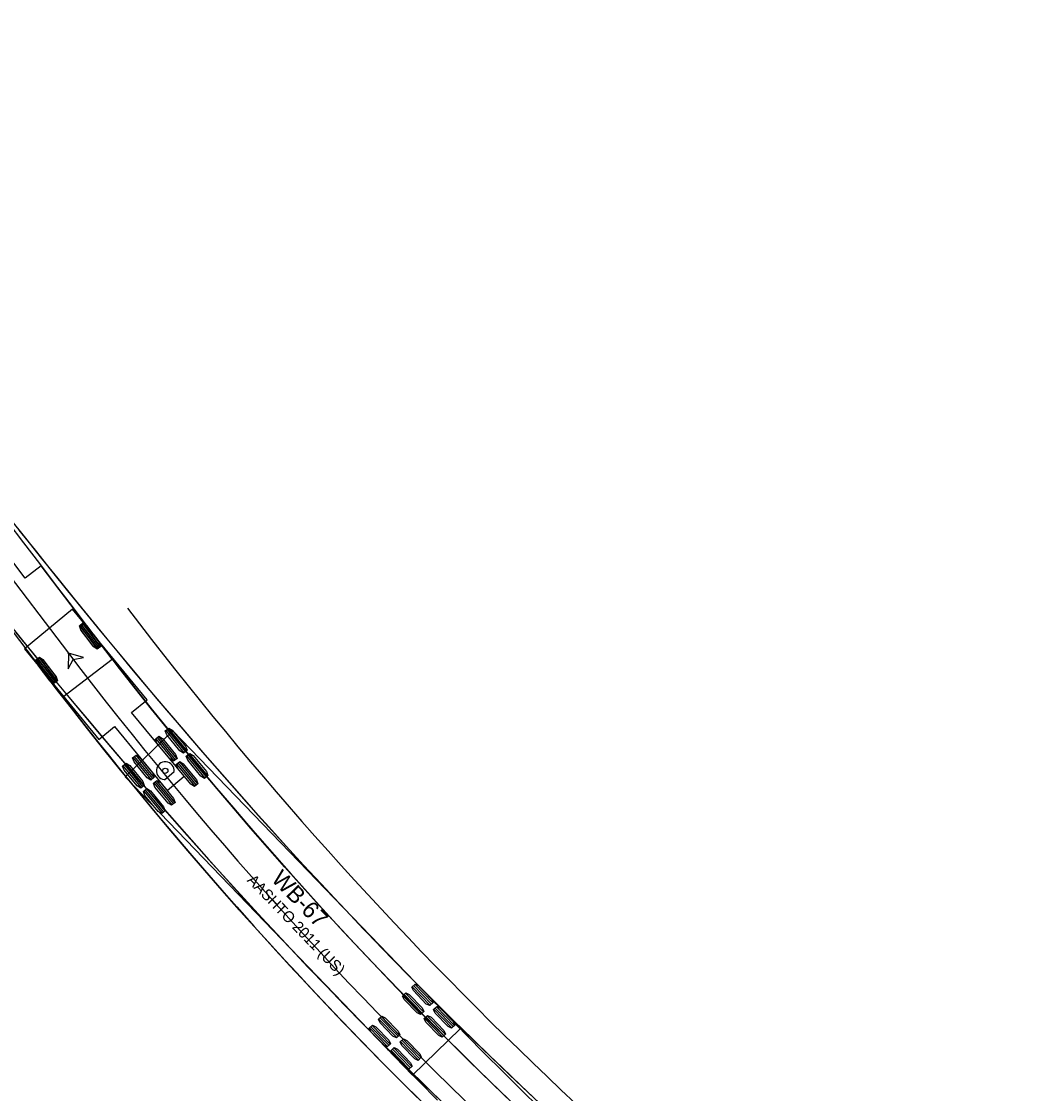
# Model space of a CAD drawing. Extents: x 916040 to 917457, y 328936 to 330267.
# Drawn here: x 916379 to 916508.8, y 330071.7 to 330208.9 of the extents above; entities that cross this region are included whole.
import ezdxf

# ---------------------------------------------------------------- set-up
doc = ezdxf.new("R2010")
doc.units = 0
for name, color, linetype in [('SB_LeftontoRoute25_WB67', 7, 'Continuous'), ('SB_RightontoRoute25_WB67_v2', 7, 'Continuous'), ('SB_ThruontonSacoRd_WB67', 7, 'Continuous'), ('WB_RightontoManchester_WB67', 7, 'Continuous')]:
    doc.layers.add(name, color=color, linetype=linetype)

msp = doc.modelspace()

# ---------------------------------------------------------------- linework, layer by layer
at = {"layer": 'SB_LeftontoRoute25_WB67'}
for p, q in [((916379.47, 330137.69), (916373.05, 330146.12)), ((916381.52, 330139.25), (916379.47, 330137.69)), ((916390.61, 330127.32), (916381.52, 330139.25)), ((916375.15, 330134.4), (916384.24, 330122.47)), ((916388.75, 330128.63), (916386.52, 330131.54)), ((916388.93, 330128.76), (916386.71, 330131.68)), ((916389.11, 330128.9), (916386.89, 330131.82)), ((916383.11, 330124.33), (916380.89, 330127.25)), ((916383.3, 330124.47), (916381.07, 330127.39)), ((916383.48, 330124.61), (916381.26, 330127.53)), ((916384.24, 330122.47), (916390.61, 330127.32)), ((916390.61, 330127.32), (916390.61, 330127.32))]:
    msp.add_line(p, q, dxfattribs=at)
for points in [[(916377.44, 330145.41), (916379.5, 330142.8), (916381.57, 330140.21), (916383.64, 330137.62), (916385.73, 330135.04), (916387.82, 330132.47), (916389.93, 330129.91), (916392.04, 330127.36), (916394.16, 330124.82), (916396.29, 330122.28), (916398.44, 330119.76), (916400.59, 330117.25), (916402.76, 330114.75), (916404.93, 330112.26), (916407.12, 330109.78), (916409.32, 330107.32), (916411.54, 330104.86), (916413.76, 330102.42), (916416, 330099.99), (916418.25, 330097.57), (916420.51, 330095.17), (916422.79, 330092.78), (916425.08, 330090.4), (916427.38, 330088.03), (916429.7, 330085.68), (916432.03, 330083.34), (916434.37, 330081.02), (916436.73, 330078.71), (916439.1, 330076.41), (916441.48, 330074.13), (916443.87, 330071.86), (916446.28, 330069.61)], [(916377.02, 330132.29), (916379.13, 330129.69), (916381.24, 330127.09), (916383.37, 330124.51), (916385.5, 330121.93), (916387.65, 330119.36), (916389.8, 330116.8), (916391.97, 330114.25), (916394.15, 330111.7), (916396.34, 330109.17), (916398.55, 330106.65), (916400.76, 330104.14), (916402.99, 330101.64), (916405.24, 330099.16), (916407.49, 330096.68), (916409.76, 330094.22), (916412.04, 330091.77), (916414.34, 330089.33), (916416.65, 330086.9), (916418.97, 330084.49), (916421.31, 330082.09), (916423.66, 330079.7), (916426.02, 330077.33), (916428.4, 330074.97), (916430.79, 330072.62), (916433.2, 330070.29)], [(916388.18, 330130.5), (916390.21, 330127.86), (916392.25, 330125.23), (916394.31, 330122.62), (916396.38, 330120.02), (916398.47, 330117.44), (916400.58, 330114.87), (916402.7, 330112.32), (916404.84, 330109.78), (916406.99, 330107.26), (916409.16, 330104.75), (916411.34, 330102.26), (916413.54, 330099.78), (916415.76, 330097.31), (916417.99, 330094.86), (916420.24, 330092.43), (916422.5, 330090.01), (916424.78, 330087.6), (916427.07, 330085.21), (916429.38, 330082.84), (916431.7, 330080.48), (916434.04, 330078.13), (916436.4, 330075.8), (916438.77, 330073.49), (916441.15, 330071.19)], [(916381.82, 330125.65), (916383.86, 330123), (916385.91, 330120.35), (916387.98, 330117.72), (916390.08, 330115.1), (916392.19, 330112.49), (916394.31, 330109.9), (916396.46, 330107.32), (916398.62, 330104.75), (916400.8, 330102.19), (916403, 330099.65), (916405.21, 330097.12), (916407.44, 330094.61), (916409.69, 330092.11), (916411.95, 330089.62), (916414.23, 330087.15), (916416.52, 330084.69), (916418.83, 330082.25), (916421.16, 330079.82), (916423.5, 330077.41), (916425.86, 330075.01), (916428.24, 330072.63), (916430.63, 330070.26)]]:
    msp.add_lwpolyline(points, dxfattribs=at)
for points in [[(916389.16, 330128.94), (916388.7, 330128.59), (916388.25, 330128.89), (916386.65, 330130.99), (916386.48, 330131.51), (916386.93, 330131.85), (916387.38, 330131.55), (916388.98, 330129.45)], [(916383.52, 330124.64), (916383.07, 330124.3), (916382.62, 330124.6), (916381.02, 330126.7), (916380.85, 330127.21), (916381.3, 330127.56), (916381.75, 330127.26), (916383.35, 330125.16)]]:
    msp.add_lwpolyline(points, close=True, dxfattribs=at)
for centre in [(916388.18, 330130.5), (916385, 330128.08), (916381.82, 330125.65)]:
    msp.add_circle(centre, 0.0417, dxfattribs=at)
msp.add_arc((916795.02, 330440.53), 515.5, 217.3089, 236.0807, dxfattribs=at)
at = {"layer": 'SB_RightontoRoute25_WB67_v2'}
msp.add_line((916323.38, 330208.94), (916385, 330128.08), dxfattribs=at)
for points in [[(916377.24, 330144.86), (916379.26, 330142.2), (916381.29, 330139.54), (916383.32, 330136.88), (916385.35, 330134.22), (916387.37, 330131.56), (916389.4, 330128.91), (916391.43, 330126.28), (916393.49, 330123.66), (916395.55, 330121.06), (916397.64, 330118.47), (916399.73, 330115.9), (916401.85, 330113.34), (916403.98, 330110.8), (916406.13, 330108.27), (916408.29, 330105.75), (916410.47, 330103.25), (916412.66, 330100.77), (916414.87, 330098.3), (916417.09, 330095.84), (916419.34, 330093.4), (916421.59, 330090.98), (916423.86, 330088.56), (916426.15, 330086.17), (916428.45, 330083.79), (916430.77, 330081.42), (916433.1, 330079.07), (916435.45, 330076.73), (916437.82, 330074.41), (916440.19, 330072.11), (916442.59, 330069.82)], [(916378.67, 330143.84), (916380.74, 330141.25), (916382.81, 330138.66), (916384.89, 330136.07), (916386.98, 330133.5), (916389.08, 330130.94), (916391.19, 330128.38), (916393.31, 330125.83), (916395.44, 330123.3), (916397.58, 330120.77), (916399.73, 330118.25), (916401.89, 330115.75), (916404.06, 330113.26), (916406.25, 330110.77), (916408.44, 330108.3), (916410.65, 330105.84), (916412.87, 330103.4), (916415.1, 330100.96), (916417.35, 330098.54), (916419.61, 330096.13), (916421.88, 330093.73), (916424.16, 330091.35), (916426.46, 330088.98), (916428.77, 330086.62), (916431.09, 330084.28), (916433.43, 330081.95), (916435.78, 330079.63), (916438.15, 330077.33), (916440.52, 330075.04), (916442.91, 330072.77), (916445.32, 330070.51)], [(916378.28, 330130.73), (916380.39, 330128.13), (916382.51, 330125.54), (916384.65, 330122.96), (916386.79, 330120.38), (916388.94, 330117.82), (916391.1, 330115.26), (916393.28, 330112.72), (916395.46, 330110.18), (916397.66, 330107.66), (916399.88, 330105.14), (916402.1, 330102.64), (916404.34, 330100.15), (916406.59, 330097.67), (916408.85, 330095.2), (916411.13, 330092.74), (916413.42, 330090.3), (916415.72, 330087.87), (916418.04, 330085.45), (916420.37, 330083.05), (916422.72, 330080.65), (916425.07, 330078.27), (916427.45, 330075.91), (916429.83, 330073.56), (916432.23, 330071.22)], [(916378.98, 330129.38), (916381.01, 330126.72), (916383.04, 330124.06), (916385.09, 330121.41), (916387.15, 330118.77), (916389.24, 330116.15), (916391.34, 330113.54), (916393.46, 330110.94), (916395.6, 330108.35), (916397.75, 330105.77), (916399.93, 330103.21), (916402.12, 330100.66), (916404.32, 330098.13), (916406.55, 330095.61), (916408.79, 330093.1), (916411.04, 330090.61), (916413.31, 330088.13), (916415.6, 330085.67), (916417.91, 330083.22), (916420.23, 330080.79), (916422.57, 330078.37), (916424.92, 330075.97), (916427.29, 330073.58), (916429.67, 330071.21)]]:
    msp.add_lwpolyline(points, dxfattribs=at)
msp.add_circle((916385, 330128.08), 0.0417, dxfattribs=at)
msp.add_circle((916385, 330128.08), 0.0417, dxfattribs=at)
msp.add_arc((916795.02, 330440.53), 515.5, 217.3089, 236.0807, dxfattribs=at)
at = {"layer": 'SB_ThruontonSacoRd_WB67'}
for p, q in [((916323.38, 330208.94), (916385, 330128.08)), ((916385.54, 330133.71), (916379.37, 330128.62)), ((916395.08, 330122.13), (916385.54, 330133.71)), ((916386.45, 330131.63), (916388.67, 330128.72)), ((916386.63, 330131.77), (916388.86, 330128.86)), ((916386.82, 330131.91), (916389.04, 330128.99)), ((916379.37, 330128.62), (916388.91, 330117.04)), ((916379.37, 330128.62), (916379.37, 330128.62)), ((916380.96, 330127.16), (916383.19, 330124.24)), ((916381.15, 330127.29), (916383.37, 330124.38)), ((916381.33, 330127.43), (916383.55, 330124.52)), ((916393.1, 330120.5), (916395.08, 330122.13)), ((916399.84, 330112.32), (916393.1, 330120.5)), ((916388.91, 330117.04), (916390.89, 330118.68)), ((916390.89, 330118.68), (916397.63, 330110.5)), ((916398.38, 330118.14), (916392.26, 330112.24)), ((916396.36, 330117.27), (916398.69, 330114.44)), ((916396.54, 330117.41), (916398.87, 330114.58)), ((916397.46, 330118.17), (916399.79, 330115.34)), ((916397.63, 330118.32), (916399.97, 330115.49)), ((916397.81, 330118.46), (916400.14, 330115.63)), ((916435.18, 330079.99), (916398.38, 330118.14)), ((916396.18, 330117.12), (916398.52, 330114.29)), ((916393.26, 330114.71), (916395.6, 330111.88)), ((916393.44, 330114.86), (916395.77, 330112.03)), ((916393.62, 330115.01), (916395.95, 330112.18)), ((916400.13, 330114.93), (916402.46, 330112.1)), ((916400.31, 330115.07), (916402.64, 330112.25)), ((916400.48, 330115.22), (916402.81, 330112.39)), ((916391.99, 330113.66), (916394.32, 330110.84)), ((916392.17, 330113.81), (916394.5, 330110.98)), ((916392.35, 330113.96), (916394.68, 330111.13)), ((916398.86, 330113.88), (916401.19, 330111.05)), ((916399.03, 330114.03), (916401.36, 330111.2)), ((916399.21, 330114.17), (916401.54, 330111.34)), ((916392.26, 330112.24), (916429.06, 330074.09)), ((916392.26, 330112.24), (916392.26, 330112.24)), ((916396.29, 330111.76), (916398.62, 330108.94)), ((916397.29, 330111.89), (916398.54, 330112.92)), ((916397.63, 330110.5), (916399.84, 330112.32)), ((916394.66, 330110.42), (916396.99, 330107.59)), ((916394.84, 330110.57), (916397.17, 330107.74)), ((916395.02, 330110.72), (916397.35, 330107.89)), ((916395.94, 330111.47), (916398.27, 330108.64)), ((916396.11, 330111.62), (916398.45, 330108.79)), ((916429.35, 330085.7), (916431.65, 330083.33)), ((916427.84, 330084.24), (916430.13, 330081.86)), ((916428, 330084.4), (916430.29, 330082.02)), ((916428.17, 330084.56), (916430.46, 330082.18)), ((916429.02, 330085.38), (916431.32, 330083.01)), ((916429.19, 330085.54), (916431.48, 330083.17)), ((916432.13, 330082.82), (916434.42, 330080.45)), ((916425.08, 330081.58), (916427.37, 330079.21)), ((916430.78, 330081.52), (916433.07, 330079.14)), ((916430.94, 330081.68), (916433.23, 330079.3)), ((916431.8, 330082.5), (916434.09, 330080.13)), ((916431.97, 330082.66), (916434.26, 330080.29)), ((916423.57, 330080.12), (916425.86, 330077.74)), ((916423.73, 330080.28), (916426.02, 330077.9)), ((916423.9, 330080.44), (916426.19, 330078.06)), ((916424.75, 330081.26), (916427.05, 330078.89)), ((916424.92, 330081.42), (916427.21, 330079.05)), ((916430.61, 330081.36), (916432.9, 330078.98)), ((916427.86, 330078.7), (916430.15, 330076.33)), ((916429.06, 330074.09), (916435.18, 330079.99)), ((916426.51, 330077.4), (916428.8, 330075.02)), ((916426.67, 330077.56), (916428.96, 330075.18)), ((916427.53, 330078.38), (916429.82, 330076.01)), ((916427.7, 330078.54), (916429.99, 330076.17)), ((916426.34, 330077.24), (916428.63, 330074.86))]:
    msp.add_line(p, q, dxfattribs=at)
for points in [[(916386.41, 330131.6), (916386.86, 330131.95), (916387.31, 330131.64), (916388.91, 330129.54), (916389.08, 330129.03), (916388.63, 330128.68), (916388.18, 330128.99), (916386.58, 330131.09)], [(916380.92, 330127.12), (916381.37, 330127.47), (916381.82, 330127.16), (916383.42, 330125.07), (916383.6, 330124.55), (916383.14, 330124.21), (916382.69, 330124.51), (916381.09, 330126.61)], [(916385, 330128.08), (916384.99, 330126.08), (916385.61, 330127.28), (916386.93, 330127.55)], [(916397.41, 330118.13), (916397.86, 330118.5), (916398.31, 330118.21), (916399.99, 330116.17), (916400.19, 330115.67), (916399.75, 330115.3), (916399.29, 330115.59), (916397.61, 330117.63)], [(916396.14, 330117.08), (916396.58, 330117.45), (916397.04, 330117.16), (916398.72, 330115.12), (916398.91, 330114.62), (916398.47, 330114.25), (916398.01, 330114.54), (916396.33, 330116.58)], [(916393.22, 330114.68), (916393.66, 330115.04), (916394.12, 330114.76), (916395.8, 330112.72), (916395.99, 330112.21), (916395.55, 330111.85), (916395.09, 330112.14), (916393.41, 330114.17)], [(916400.09, 330114.89), (916400.53, 330115.26), (916400.99, 330114.97), (916402.67, 330112.93), (916402.86, 330112.43), (916402.42, 330112.06), (916401.96, 330112.35), (916400.28, 330114.39)], [(916391.95, 330113.63), (916392.39, 330113.99), (916392.85, 330113.71), (916394.53, 330111.67), (916394.72, 330111.16), (916394.28, 330110.8), (916393.82, 330111.09), (916392.14, 330113.12)], [(916398.81, 330113.84), (916399.25, 330114.21), (916399.71, 330113.92), (916401.39, 330111.88), (916401.59, 330111.38), (916401.14, 330111.01), (916400.68, 330111.3), (916399.01, 330113.34)], [(916395.89, 330111.44), (916396.33, 330111.8), (916396.79, 330111.51), (916398.47, 330109.48), (916398.67, 330108.97), (916398.22, 330108.61), (916397.76, 330108.89), (916396.09, 330110.93)], [(916394.62, 330110.39), (916395.06, 330110.75), (916395.52, 330110.46), (916397.2, 330108.43), (916397.39, 330107.92), (916396.95, 330107.56), (916396.49, 330107.84), (916394.81, 330109.88)], [(916428.98, 330085.34), (916429.39, 330085.74), (916429.84, 330085.53), (916431.49, 330083.82), (916431.69, 330083.37), (916431.27, 330082.97), (916430.83, 330083.18), (916429.18, 330084.89)], [(916427.8, 330084.2), (916428.21, 330084.59), (916428.65, 330084.38), (916430.3, 330082.67), (916430.5, 330082.22), (916430.09, 330081.82), (916429.64, 330082.04), (916427.99, 330083.75)], [(916431.76, 330082.46), (916432.17, 330082.86), (916432.62, 330082.65), (916434.27, 330080.94), (916434.46, 330080.49), (916434.05, 330080.09), (916433.61, 330080.3), (916431.96, 330082.01)], [(916424.71, 330081.22), (916425.12, 330081.62), (916425.57, 330081.41), (916427.22, 330079.7), (916427.42, 330079.25), (916427, 330078.85), (916426.56, 330079.06), (916424.91, 330080.77)], [(916430.57, 330081.32), (916430.98, 330081.72), (916431.43, 330081.5), (916433.08, 330079.79), (916433.28, 330079.34), (916432.86, 330078.94), (916432.42, 330079.16), (916430.77, 330080.87)], [(916423.53, 330080.08), (916423.94, 330080.48), (916424.38, 330080.26), (916426.03, 330078.55), (916426.23, 330078.1), (916425.82, 330077.7), (916425.37, 330077.92), (916423.72, 330079.63)], [(916427.49, 330078.35), (916427.9, 330078.74), (916428.35, 330078.53), (916430, 330076.82), (916430.19, 330076.37), (916429.78, 330075.97), (916429.34, 330076.18), (916427.69, 330077.89)], [(916426.3, 330077.2), (916426.71, 330077.6), (916427.16, 330077.38), (916428.81, 330075.67), (916429.01, 330075.22), (916428.59, 330074.82), (916428.15, 330075.04), (916426.5, 330076.75)]]:
    msp.add_lwpolyline(points, close=True, dxfattribs=at)
for points in [[(916442.66, 330069.74), (916440.27, 330072.03), (916437.89, 330074.34), (916435.53, 330076.66), (916433.18, 330079), (916430.84, 330081.35), (916428.53, 330083.71), (916426.22, 330086.09), (916423.94, 330088.49), (916421.66, 330090.9), (916419.41, 330093.32), (916417.17, 330095.76), (916414.94, 330098.22), (916412.73, 330100.68), (916410.54, 330103.17), (916408.37, 330105.66), (916406.21, 330108.17), (916404.06, 330110.7), (916401.93, 330113.24), (916399.82, 330115.79), (916397.73, 330118.35), (916395.65, 330120.93), (916393.59, 330123.53), (916391.55, 330126.13), (916389.52, 330128.75), (916388.11, 330130.59)], [(916430.07, 330070.81), (916427.69, 330073.18), (916425.31, 330075.57), (916422.96, 330077.97), (916420.62, 330080.38), (916418.3, 330082.81), (916415.99, 330085.26), (916413.7, 330087.72), (916411.42, 330090.2), (916409.16, 330092.69), (916406.92, 330095.2), (916404.69, 330097.72), (916402.48, 330100.25), (916400.28, 330102.8), (916398.1, 330105.36), (916395.94, 330107.94), (916393.8, 330110.53), (916391.67, 330113.13), (916389.56, 330115.75), (916387.46, 330118.39), (916385.38, 330121.03), (916383.32, 330123.69), (916381.89, 330125.56)], [(916445.33, 330069.9), (916442.97, 330072.21), (916440.62, 330074.53), (916438.29, 330076.86), (916435.97, 330079.21), (916433.66, 330081.57), (916432.05, 330083.23)], [(916432.26, 330070.87), (916429.91, 330073.25), (916427.57, 330075.65), (916425.94, 330077.33)]]:
    msp.add_lwpolyline(points, dxfattribs=at)
for centre, radius in [((916388.11, 330130.59), 0.0417), ((916385, 330128.08), 0.0417), ((916381.89, 330125.56), 0.0417), ((916397.4, 330113.03), 0.34), ((916432.05, 330083.23), 0.0417), ((916425.94, 330077.33), 0.0417)]:
    msp.add_circle(centre, radius, dxfattribs=at)
for centre, radius, start, end in [((916795.02, 330440.53), 515.5, 217.3089, 236.0807), ((916397.4, 330113.03), 1.14, 354.4942, 264.4942)]:
    msp.add_arc(centre, radius, start, end, dxfattribs=at)
at = {"layer": 'WB_RightontoManchester_WB67'}
msp.add_arc((916795.02, 330440.53), 506, 217.3089, 235.5571, dxfattribs=at)

# ---------------------------------------------------------------- texts
at = {"layer": 'SB_ThruontonSacoRd_WB67'}
for s, height, p in [('AASHTO 2011 (US)', 1.4167, (916407.79, 330098.94)), ('WB-67', 2.125, (916410.87, 330099.06))]:
    msp.add_text(s, height=height, rotation=313.9723, dxfattribs=at).set_placement(p)

doc.saveas('drawing.dxf')
